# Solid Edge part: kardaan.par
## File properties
Author: Türk
Template: Iso Part.par
Last saved by: Türk
Revision: 25
Application: Solid Edge
Accuracy: 0,990
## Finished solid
Body 1: solid body, 43 faces, 98 edges, 56 vertices.
  Faces by surface: plane 28, cylinder 15
  Edges by curve: line 68, circle 30
Bounding box of the edges (mm): 64.000 x 755.900 x 64.000, from (-32, -535.9, -32) to (32, 220, 32).
Cylindrical faces by radius (mm): R7.5 x4, R10 x8, R27.5 x1, R32 x2
Planar faces by outward normal: +x 4, +y 4, +z 4, -x 4, -y 4, -z 4, oblique 4
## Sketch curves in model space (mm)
line (-27.5, 170, -27.5) -> (-27.5, 170, 27.5)
line (-27.5, 170, 27.5) -> (27.5, 170, 27.5)
line (27.5, 170, 27.5) -> (27.5, 170, -27.5)
line (27.5, 170, -27.5) -> (-27.5, 170, -27.5)
line (-27.5, 220, 0) -> (-27.5, 205, 0)
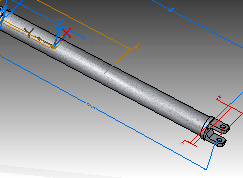
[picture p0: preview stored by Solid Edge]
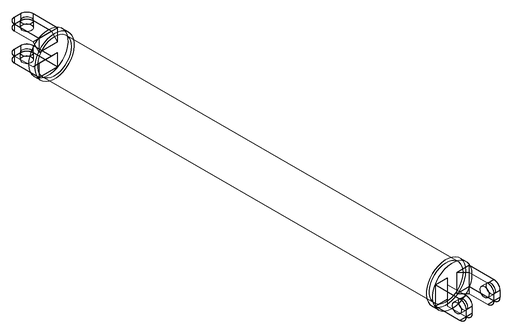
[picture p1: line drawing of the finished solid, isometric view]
